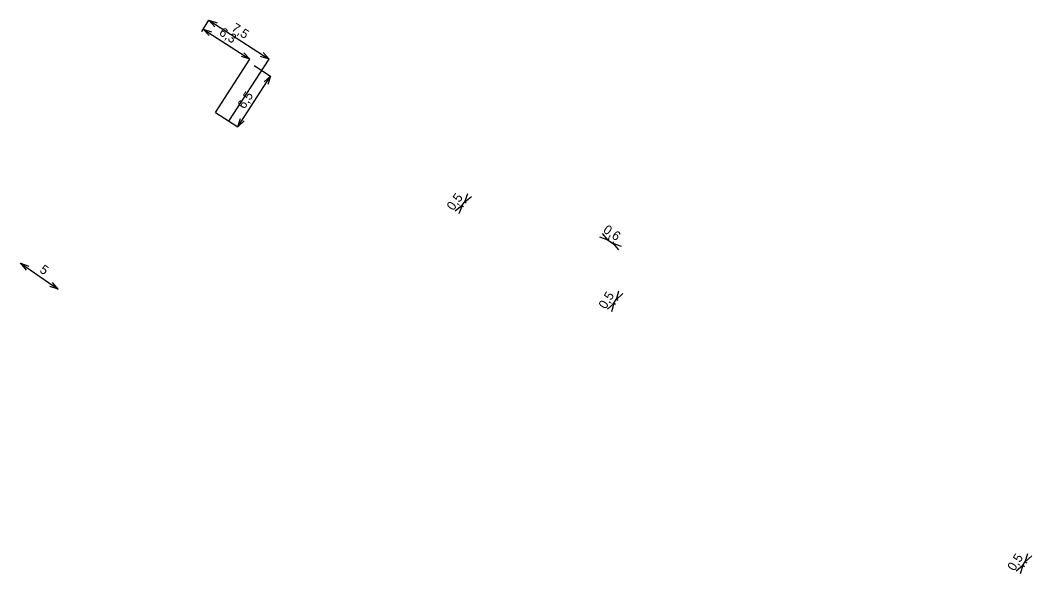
# Model space of a CAD drawing. Extents: x -742845 to -742557, y -1054636 to -1054473.
# Drawn here: x -742667 to -742556.6, y -1054582.4 to -1054522.1 of the extents above; entities that cross this region are included whole.
import ezdxf

# ---------------------------------------------------------------- set-up
doc = ezdxf.new("R2010")
doc.units = 0
doc.layers.add('Kota_NN', color=7, linetype='Continuous')

msp = doc.modelspace()

# ---------------------------------------------------------------- linework, layer by layer
at = {"layer": 'Kota_NN'}
for p, q in [((-742647.17, -1054523.29), (-742646.38, -1054522.07)), ((-742646.38, -1054522.07), (-742639.83, -1054526.32)), ((-742646.38, -1054522.07), (-742645.47, -1054522.37)), ((-742646.38, -1054522.07), (-742645.74, -1054522.79)), ((-742647.17, -1054523.29), (-742647.01, -1054523.04)), ((-742647.01, -1054523.04), (-742641.93, -1054526.33)), ((-742647.01, -1054523.04), (-742646.09, -1054523.33)), ((-742647.01, -1054523.04), (-742646.36, -1054523.75)), ((-742645.68, -1054532.11), (-742641.93, -1054526.33)), ((-742644.2, -1054533.06), (-742639.83, -1054526.32)), ((-742641.93, -1054526.33), (-742642.84, -1054526.03)), ((-742641.93, -1054526.33), (-742642.57, -1054525.61)), ((-742639.83, -1054526.32), (-742640.75, -1054526.02)), ((-742639.83, -1054526.32), (-742640.48, -1054525.6)), ((-742641.44, -1054527), (-742639.66, -1054528.16)), ((-742643.24, -1054533.69), (-742639.66, -1054528.16)), ((-742639.66, -1054528.16), (-742640.37, -1054528.8)), ((-742639.66, -1054528.16), (-742639.95, -1054529.07)), ((-742645.68, -1054532.11), (-742643.24, -1054533.69)), ((-742643.24, -1054533.69), (-742642.95, -1054532.78)), ((-742643.24, -1054533.69), (-742642.53, -1054533.05)), ((-742618.49, -1054541.86), (-742618.14, -1054540.96)), ((-742618.9, -1054542.42), (-742618.37, -1054541.7)), ((-742618.55, -1054541.81), (-742618.33, -1054541.98)), ((-742618.49, -1054541.86), (-742617.74, -1054541.26)), ((-742618.78, -1054542.26), (-742619.53, -1054542.86)), ((-742618.78, -1054542.26), (-742619.13, -1054543.16)), ((-742618.84, -1054542.22), (-742618.62, -1054542.38)), ((-742602.84, -1054546.03), (-742603.47, -1054545.3)), ((-742602.84, -1054546.03), (-742603.75, -1054545.71)), ((-742603.01, -1054545.92), (-742602.18, -1054546.47)), ((-742602.85, -1054546.04), (-742602.73, -1054545.86)), ((-742602.35, -1054546.38), (-742602.23, -1054546.2)), ((-742602.34, -1054546.36), (-742601.44, -1054546.68)), ((-742602.34, -1054546.36), (-742601.71, -1054547.09)), ((-742666.96, -1054548.59), (-742666.94, -1054548.56)), ((-742666.94, -1054548.56), (-742662.83, -1054551.39)), ((-742666.94, -1054548.56), (-742666.04, -1054548.88)), ((-742666.94, -1054548.56), (-742666.32, -1054549.29)), ((-742662.83, -1054551.39), (-742663.45, -1054550.66)), ((-742662.83, -1054551.39), (-742663.73, -1054551.07)), ((-742662.84, -1054551.42), (-742662.83, -1054551.39)), ((-742601.95, -1054552.49), (-742601.67, -1054551.57)), ((-742601.95, -1054552.49), (-742601.25, -1054551.83)), ((-742602.22, -1054552.92), (-742602.92, -1054553.57)), ((-742602.22, -1054552.92), (-742602.49, -1054553.84)), ((-742602.32, -1054553.09), (-742601.85, -1054552.32)), ((-742602.27, -1054552.88), (-742602.05, -1054553.02)), ((-742602.01, -1054552.46), (-742601.78, -1054552.59)), ((-742557.37, -1054581.09), (-742557.07, -1054580.18)), ((-742557.37, -1054581.09), (-742556.65, -1054580.45)), ((-742557.62, -1054581.48), (-742558.34, -1054582.11)), ((-742557.62, -1054581.48), (-742557.92, -1054582.39)), ((-742557.73, -1054581.64), (-742557.26, -1054580.92)), ((-742557.64, -1054581.46), (-742557.45, -1054581.58)), ((-742557.39, -1054581.07), (-742557.2, -1054581.2))]:
    msp.add_line(p, q, dxfattribs=at)

# ---------------------------------------------------------------- texts
for s, rotation, p in [('6,3', 327.0518, (-742645.36, -1054523.62)), ('7,5', 327.0517, (-742644, -1054523.14)), ('6,5', 57.0514, (-742642.51, -1054531.82)), ('0,5', 53.7383, (-742619.74, -1054542.89)), ('0,6', 326.0552, (-742603.47, -1054545.12)), ('5', 325.4531, (-742664.93, -1054549.46)), ('0,5', 58.2732, (-742603.12, -1054553.62)), ('0,5', 56.7182, (-742558.56, -1054582.17))]:
    msp.add_text(s, height=1, rotation=rotation, dxfattribs=at).set_placement(p)

doc.saveas('drawing.dxf')
